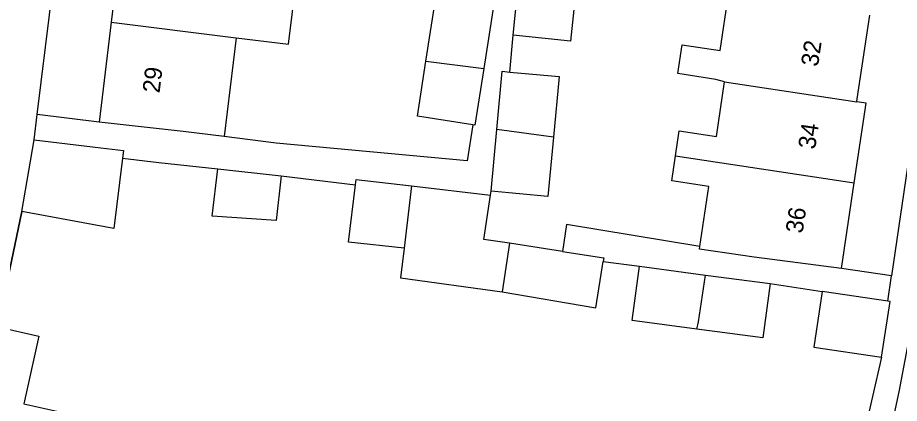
# Model space of a CAD drawing. Extents: x 162172 to 163187, y 382874 to 383684.
# Drawn here: x 162849.7 to 162900.7, y 383155.7 to 383178 of the extents above; entities that cross this region are included whole.
import ezdxf

# ---------------------------------------------------------------- set-up
doc = ezdxf.new("R2010")
doc.units = 0
for name, color, linetype in [('IMGEO_Muur', 7, 'Continuous'), ('IMGEO_Pand', 7, 'Continuous'), ('IMGEO_Pand_nummerreeks', 7, 'Continuous'), ('IMGEO_Voetpad_open', 7, 'Continuous')]:
    doc.layers.add(name, color=color, linetype=linetype)

msp = doc.modelspace()

# ---------------------------------------------------------------- linework, layer by layer
at = {"layer": 'IMGEO_Muur'}
msp.add_lwpolyline([(162849.921, 383166.83), (162848.509, 383160.165)], dxfattribs=at)
at = {"layer": 'IMGEO_Pand'}
for points in [[(162856.431, 383183.382), (162855.777, 383183.463), (162855.088, 383177.781)], [(162862.337, 383176.882), (162865.351, 383176.508), (162866.067, 383182.297), (162864.402, 383182.503)], [(162878.378, 383177.023), (162878.802, 383181.227)], [(162882.106, 383180.729), (162881.698, 383176.688), (162878.378, 383177.023)], [(162873.317, 383175.52), (162873.916, 383179.344), (162876.952, 383178.868)], [(162890.614, 383174.338), (162890.103, 383174.477), (162887.902, 383174.809), (162888.153, 383176.475), (162890.354, 383176.143), (162890.848, 383179.411)], [(162876.952, 383178.868), (162877.252, 383178.821), (162876.67, 383175.104)], [(162898.262, 383173.184), (162898.287, 383173.348), (162899.019, 383178.179)], [(162855.088, 383177.781), (162854.387, 383171.998)], [(162855.088, 383177.781), (162862.337, 383176.882)], [(162862.337, 383176.882), (162861.63, 383171.166)], [(162876.041, 383171.846), (162872.821, 383172.351), (162873.317, 383175.52)], [(162873.317, 383175.52), (162876.67, 383175.104)], [(162876.67, 383175.104), (162876.157, 383171.828), (162876.041, 383171.846)], [(162877.425, 383171.571), (162877.741, 383174.941), (162878.179, 383174.9)], [(162878.179, 383174.9), (162881.033, 383174.633), (162880.705, 383171.127)], [(162887.767, 383170.059), (162887.984, 383171.498), (162890.136, 383171.174), (162890.614, 383174.338)], [(162890.614, 383174.338), (162898.262, 383173.184)], [(162898.116, 383168.497), (162898.806, 383173.102), (162898.262, 383173.184)], [(162861.63, 383171.166), (162859.268, 383171.458), (162854.387, 383171.998)], [(162877.092, 383168.016), (162877.425, 383171.571)], [(162880.705, 383171.127), (162877.425, 383171.571)], [(162849.921, 383166.83), (162850.623, 383170.976)], [(162850.623, 383170.976), (162854.499, 383170.523), (162855.803, 383170.362), (162855.749, 383169.928)], [(162880.705, 383171.127), (162880.384, 383167.707), (162877.092, 383168.016)], [(162855.749, 383169.928), (162855.245, 383165.846), (162849.921, 383166.83)], [(162889.175, 383164.804), (162889.7, 383168.281), (162887.548, 383168.606), (162887.767, 383170.059)], [(162887.767, 383170.059), (162898.116, 383168.497)], [(162864.928, 383168.889), (162864.644, 383166.308), (162860.934, 383166.573), (162861.258, 383169.293)], [(162861.258, 383169.293), (162864.928, 383168.889)], [(162872.055, 383164.713), (162868.834, 383165.063), (162869.231, 383168.373)], [(162869.231, 383168.373), (162869.269, 383168.689), (162872.486, 383168.31)], [(162872.486, 383168.31), (162872.055, 383164.713)], [(162872.486, 383168.31), (162877.058, 383167.771)], [(162897.374, 383163.545), (162898.116, 383168.497)], [(162878.157, 383164.994), (162876.672, 383165.222), (162877.058, 383167.771)], [(162872.055, 383164.713), (162871.85, 383162.998), (162877.731, 383162.18)], [(162878.157, 383164.994), (162877.731, 383162.18)], [(162881.225, 383164.523), (162878.157, 383164.994)], [(162897.374, 383163.545), (162892.319, 383164.185), (162889.154, 383164.662), (162889.175, 383164.804)], [(162881.225, 383164.523), (162883.61, 383164.156), (162883.578, 383163.952)], [(162877.731, 383162.18), (162883.16, 383161.259), (162883.578, 383163.952)], [(162889.008, 383160.031), (162885.268, 383160.529), (162885.69, 383163.671)], [(162885.69, 383163.671), (162889.511, 383163.162)], [(162889.008, 383160.031), (162889.101, 383160.457), (162889.511, 383163.162)], [(162889.511, 383163.162), (162893.255, 383162.664)], [(162893.255, 383162.664), (162892.833, 383159.521), (162889.008, 383160.031)], [(162896.263, 383162.216), (162895.777, 383158.995), (162899.697, 383158.408)], [(162900.06, 383161.648), (162896.263, 383162.216)], [(162899.697, 383158.408), (162900.192, 383161.628), (162900.06, 383161.648)], [(162848.509, 383160.165), (162850.908, 383159.623), (162850.042, 383155.703), (162853.153, 383155.022)]]:
    msp.add_lwpolyline(points, dxfattribs=at)
at = {"layer": 'IMGEO_Voetpad_open'}
for points in [[(162850.805, 383172.442), (162859.396, 383241.785), (162859.74, 383244.698)], [(162906.505, 383205.532), (162900.276, 383163.119)], [(162878.179, 383174.9), (162878.378, 383177.023)], [(162850.623, 383170.976), (162850.805, 383172.442)], [(162854.387, 383171.998), (162850.805, 383172.442)], [(162876.041, 383171.846), (162875.713, 383169.755), (162864.642, 383170.792), (162861.63, 383171.166)], [(162855.749, 383169.928), (162857.851, 383169.668), (162861.258, 383169.293)], [(162864.928, 383168.889), (162869.231, 383168.373)], [(162877.058, 383167.771), (162877.092, 383168.016)], [(162848.509, 383160.165), (162849.921, 383166.83)], [(162889.175, 383164.804), (162881.465, 383166.084), (162881.225, 383164.523)], [(162883.578, 383163.952), (162885.69, 383163.671)], [(162900.276, 383163.119), (162897.374, 383163.545)], [(162893.255, 383162.664), (162896.263, 383162.216)], [(162900.06, 383161.648), (162900.276, 383163.119)], [(162896.768, 383138.028), (162900.715, 383156.409), (162901.688, 383161.501)], [(162899.697, 383158.408), (162898.651, 383153.856), (162897.653, 383149.297)]]:
    msp.add_lwpolyline(points, dxfattribs=at)

# ---------------------------------------------------------------- texts
at = {"layer": 'IMGEO_Pand_nummerreeks'}
for s, rotation, p in [('32', 81.3887, (162896.016, 383175.177)), ('29', 83.0846, (162857.89, 383173.65)), ('34', 81.4746, (162895.853, 383170.392)), ('36', 81.4746, (162895.124, 383165.531))]:
    msp.add_text(s, height=1, rotation=rotation, dxfattribs=at).set_placement(p)

doc.saveas('drawing.dxf')
